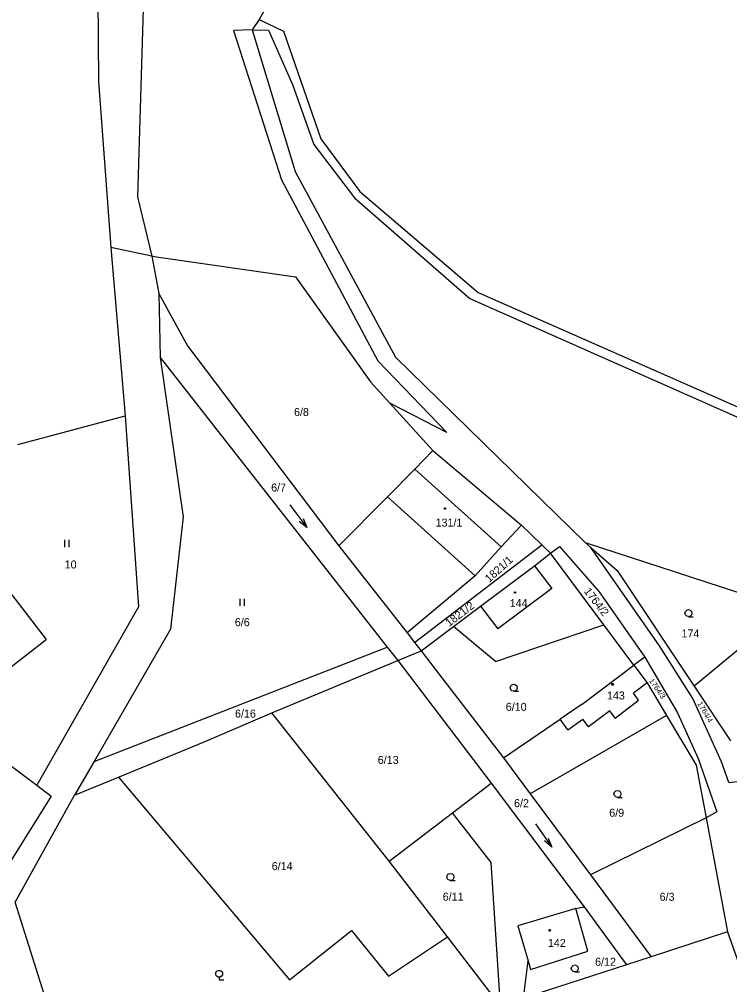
# Model space of a CAD drawing. Extents: x -799786 to -795190, y -1021716 to -1017834.
# Drawn here: x -797930.9 to -797780.2, y -1018913.6 to -1018708.6 of the extents above; entities that cross this region are included whole.
import ezdxf

# ---------------------------------------------------------------- set-up
doc = ezdxf.new("R2010")
doc.units = 0
for name, color, linetype in [('Default', 7, 'Continuous'), ('KN_HRANICE', 7, 'Continuous'), ('KN_KULTURY', 7, 'Continuous'), ('KN_PARCELY', 7, 'Continuous'), ('KN_SLUCKY', 7, 'Continuous')]:
    doc.layers.add(name, color=color, linetype=linetype)

# ---------------------------------------------------------------- blocks, each defined once
blk = doc.blocks.new('304')
at = {"layer": 'Default'}
blk.add_lwpolyline([(0, 0), (-0.38, 0.1), (-0.65, 0.37), (-0.75, 0.74), (-0.65, 1.11), (-0.38, 1.38), (-0.01, 1.48), (0.36, 1.38), (0.63, 1.11), (0.73, 0.73), (0.63, 0.35), (0.36, 0.08), (-0.02, -0.02), (0.98, -0.02)], dxfattribs=at)
blk = doc.blocks.new('305')
at = {"layer": 'Default'}
blk.add_lwpolyline([(0, 0.53), (-0.19, 0.53), (-0.53, 0.72), (-0.72, 1.06), (-0.72, 1.45), (-0.53, 1.79), (-0.19, 1.98), (0.2, 1.98), (0.54, 1.79), (0.73, 1.45), (0.73, 1.06), (0.54, 0.72), (0.2, 0.53), (0.01, 0.53), (0.01, 0), (1.01, 0)], dxfattribs=at)
blk = doc.blocks.new('306')
at = {"layer": 'Default'}
for p, q in [((-0.5, 1.5), (-0.5, 0)), ((0.5, 0), (0.5, 1.5))]:
    blk.add_line(p, q, dxfattribs=at)
blk = doc.blocks.new('802')
at = {"layer": 'Default'}
blk.add_line((-3, 0), (3, 0), dxfattribs=at)
blk.add_lwpolyline([(1, 0.5), (3, 0), (1, -0.5)], dxfattribs=at)
blk = doc.blocks.new('402')
at = {"layer": 'Default'}
blk.add_lwpolyline([(0.09, 0.15), (0.18, 0), (0.09, -0.15), (-0.09, -0.15), (-0.18, 0), (-0.09, 0.15), (0.09, 0.15)], dxfattribs=at)

msp = doc.modelspace()

# ---------------------------------------------------------------- linework, layer by layer
at = {"layer": 'KN_HRANICE'}
for p, q in [((-797902.79, -1018644.81), (-797905.77, -1018746.29)), ((-797914.78, -1018646.59), (-797914.05, -1018721.83)), ((-797878.74, -1018706.41), (-797879.96, -1018708.66)), ((-797879.96, -1018708.66), (-797881.5, -1018710.9)), ((-797879.96, -1018708.66), (-797874.8, -1018711.12)), ((-797881.5, -1018710.9), (-797885.45, -1018710.98)), ((-797885.45, -1018710.98), (-797875.25, -1018742.68)), ((-797881.5, -1018710.9), (-797878.03, -1018710.96)), ((-797881.5, -1018710.9), (-797872.36, -1018740.96)), ((-797878.03, -1018710.96), (-797872.93, -1018722.5)), ((-797874.8, -1018711.12), (-797866.9, -1018733.99)), ((-797914.05, -1018721.83), (-797911.48, -1018757.08)), ((-797872.93, -1018722.5), (-797868.41, -1018735.2)), ((-797868.41, -1018735.2), (-797859.73, -1018746.53)), ((-797866.9, -1018733.99), (-797858.62, -1018745.17)), ((-797872.36, -1018740.96), (-797851.04, -1018780.39)), ((-797875.25, -1018742.68), (-797854.8, -1018781.15)), ((-797858.62, -1018745.17), (-797833.49, -1018766.66)), ((-797905.77, -1018746.29), (-797902.78, -1018758.93)), ((-797859.73, -1018746.53), (-797835.29, -1018767.9)), ((-797911.48, -1018757.08), (-797908.42, -1018792.81)), ((-797902.78, -1018758.93), (-797901.25, -1018766.87)), ((-797902.78, -1018758.93), (-797872.27, -1018763.32)), ((-797872.27, -1018763.32), (-797856.35, -1018785.57)), ((-797901.25, -1018766.87), (-797901.03, -1018780.44)), ((-797901.25, -1018766.87), (-797895.18, -1018777.94)), ((-797835.29, -1018767.9), (-797771.75, -1018796.11)), ((-797833.49, -1018766.66), (-797771.73, -1018793.9)), ((-797895.18, -1018777.94), (-797863.08, -1018820.42)), ((-797901.03, -1018780.44), (-797896.14, -1018814.23)), ((-797901.03, -1018780.44), (-797852.81, -1018841.93)), ((-797851.04, -1018780.39), (-797810.84, -1018819.71)), ((-797854.8, -1018781.15), (-797840.2, -1018796.33)), ((-797856.35, -1018785.57), (-797852.27, -1018790.1)), ((-797852.27, -1018790.1), (-797843.13, -1018800.15)), ((-797840.2, -1018796.33), (-797852.27, -1018790.1)), ((-797931.22, -1018798.88), (-797908.42, -1018792.81)), ((-797908.42, -1018792.81), (-797905.56, -1018833.37)), ((-797843.13, -1018800.15), (-797846.98, -1018804.16)), ((-797843.13, -1018800.15), (-797824.36, -1018816.02)), ((-797846.98, -1018804.16), (-797852.79, -1018810.03)), ((-797947.79, -1018811.02), (-797925.16, -1018840.33)), ((-797852.79, -1018810.03), (-797863.08, -1018820.42)), ((-797896.14, -1018814.23), (-797898.83, -1018838.12)), ((-797828.64, -1018820.64), (-797824.36, -1018816.02)), ((-797824.36, -1018816.02), (-797820.02, -1018820.2)), ((-797810.84, -1018819.71), (-797771.98, -1018832.39)), ((-797810.84, -1018819.71), (-797809.64, -1018820.76)), ((-797863.08, -1018820.42), (-797848.62, -1018838.85)), ((-797847.01, -1018840.91), (-797820.02, -1018820.2)), ((-797828.64, -1018820.64), (-797834.15, -1018826.78)), ((-797820.02, -1018820.2), (-797818.19, -1018821.97)), ((-797809.64, -1018820.76), (-797804, -1018825.66)), ((-797795.03, -1018841.64), (-797809.64, -1018820.76)), ((-797821.59, -1018824.67), (-797818.19, -1018821.97)), ((-797806.87, -1018837.17), (-797818.19, -1018821.97)), ((-797833, -1018833.24), (-797821.59, -1018824.67)), ((-797804, -1018825.66), (-797787.67, -1018850.19)), ((-797834.15, -1018826.78), (-797848.62, -1018838.85)), ((-797905.56, -1018833.37), (-797927.17, -1018871.24)), ((-797838.74, -1018837.55), (-797833, -1018833.24)), ((-797898.83, -1018838.12), (-797915.03, -1018866.23)), ((-797845.6, -1018842.71), (-797838.74, -1018837.55)), ((-797829.85, -1018844.95), (-797838.74, -1018837.55)), ((-797829.85, -1018844.95), (-797806.87, -1018837.17)), ((-797800.5, -1018845.72), (-797806.87, -1018837.17)), ((-797933.51, -1018846.78), (-797925.16, -1018840.33)), ((-797848.62, -1018838.85), (-797847.01, -1018840.91)), ((-797774.28, -1018839.06), (-797787.67, -1018850.19)), ((-797915.03, -1018866.23), (-797852.81, -1018841.93)), ((-797852.81, -1018841.93), (-797850.58, -1018844.77)), ((-797847.01, -1018840.91), (-797845.6, -1018842.71)), ((-797787.96, -1018852.82), (-797795.03, -1018841.64)), ((-797850.58, -1018844.77), (-797845.6, -1018842.71)), ((-797845.6, -1018842.71), (-797841.91, -1018847.5)), ((-797798.16, -1018844.08), (-797800.5, -1018845.72)), ((-797877.33, -1018855.84), (-797850.58, -1018844.77)), ((-797850.58, -1018844.77), (-797830.78, -1018870.8)), ((-797811.46, -1018854.01), (-797800.5, -1018845.72)), ((-797800.5, -1018845.72), (-797797.7, -1018849.5)), ((-797841.91, -1018847.5), (-797828.13, -1018865.39)), ((-797797.7, -1018849.5), (-797793.56, -1018856.45)), ((-797787.67, -1018850.19), (-797779.96, -1018861.78)), ((-797811.46, -1018854.01), (-797816.16, -1018857.22)), ((-797781.88, -1018866.24), (-797787.96, -1018852.82)), ((-797888.8, -1018860.85), (-797877.33, -1018855.84)), ((-797852.4, -1018887.34), (-797877.33, -1018855.84)), ((-797793.56, -1018856.45), (-797822.46, -1018873.06)), ((-797793.56, -1018856.45), (-797787.29, -1018866.96)), ((-797828.13, -1018865.39), (-797816.16, -1018857.22)), ((-797909.84, -1018869.53), (-797891.81, -1018862.08)), ((-797891.81, -1018862.08), (-797888.8, -1018860.85)), ((-797934.53, -1018865.68), (-797927.17, -1018871.24)), ((-797915.03, -1018866.23), (-797919.15, -1018873.38)), ((-797828.13, -1018865.39), (-797822.46, -1018873.06)), ((-797787.29, -1018866.96), (-797785.17, -1018878.15)), ((-797780.36, -1018870.66), (-797781.88, -1018866.24)), ((-797919.15, -1018873.38), (-797909.84, -1018869.53)), ((-797909.84, -1018869.53), (-797873.59, -1018912.55)), ((-797839, -1018877.09), (-797830.78, -1018870.8)), ((-797830.78, -1018870.8), (-797811.04, -1018897.02)), ((-797780.36, -1018870.66), (-797776.1, -1018870.15)), ((-797927.17, -1018871.24), (-797924.14, -1018873.53)), ((-797822.46, -1018873.06), (-797809.72, -1018890.27)), ((-797924.14, -1018873.53), (-797947.51, -1018911.01)), ((-797931.74, -1018896.06), (-797919.15, -1018873.38)), ((-797852.4, -1018887.34), (-797839, -1018877.09)), ((-797830.76, -1018887.66), (-797839, -1018877.09)), ((-797785.17, -1018878.15), (-797809.72, -1018890.27)), ((-797785.17, -1018878.15), (-797780.6, -1018902.35)), ((-797840.06, -1018903.4), (-797852.4, -1018887.34)), ((-797828.8, -1018918.06), (-797830.76, -1018887.66)), ((-797809.72, -1018890.27), (-797796.84, -1018907.67)), ((-797921.5, -1018928.71), (-797931.74, -1018896.06)), ((-797812.83, -1018897.4), (-797811.04, -1018897.02)), ((-797810.28, -1018906.45), (-797812.83, -1018897.4)), ((-797811.04, -1018897.02), (-797802.04, -1018909.37)), ((-797873.59, -1018912.55), (-797860.43, -1018902.08)), ((-797860.43, -1018902.08), (-797852.53, -1018911.79)), ((-797852.53, -1018911.79), (-797840.06, -1018903.4)), ((-797828.8, -1018918.06), (-797840.06, -1018903.4)), ((-797780.6, -1018902.35), (-797796.84, -1018907.67)), ((-797780.6, -1018902.35), (-797774.45, -1018919.96)), ((-797822.39, -1018910.39), (-797810.28, -1018906.45)), ((-797796.84, -1018907.67), (-797802.04, -1018909.37)), ((-797823.92, -1018916.47), (-797822.94, -1018908.49)), ((-797802.04, -1018909.37), (-797823.92, -1018916.47)), ((-797822.94, -1018908.49), (-797822.39, -1018910.39))]:
    msp.add_line(p, q, dxfattribs=at)
for points in [[(-797818.19, -1018821.97), (-797816.27, -1018820.56), (-797807.83, -1018830.19), (-797798.16, -1018844.08)], [(-797798.16, -1018844.08), (-797791.21, -1018855.9), (-797786.82, -1018865.59), (-797782.9, -1018876.91), (-797785.17, -1018878.15)]]:
    msp.add_lwpolyline(points, dxfattribs=at)
at = {"layer": 'KN_SLUCKY'}
for p, q in [((-797902.78, -1018758.93), (-797911.48, -1018757.08)), ((-797846.98, -1018804.16), (-797828.64, -1018820.64)), ((-797852.79, -1018810.03), (-797834.15, -1018826.78)), ((-797821.59, -1018824.67), (-797817.91, -1018829.47)), ((-797817.91, -1018829.47), (-797829.33, -1018838.02)), ((-797833, -1018833.24), (-797829.33, -1018838.02)), ((-797797.7, -1018849.5), (-797800.6, -1018851.69)), ((-797799.49, -1018853.19), (-797800.6, -1018851.69)), ((-797804.49, -1018856.97), (-797799.49, -1018853.19)), ((-797805.6, -1018855.46), (-797808.67, -1018857.78)), ((-797804.49, -1018856.97), (-797805.6, -1018855.46)), ((-797814.47, -1018859.51), (-797816.16, -1018857.22)), ((-797814.47, -1018859.51), (-797811.34, -1018857.18)), ((-797810.1, -1018858.86), (-797811.34, -1018857.18)), ((-797808.67, -1018857.78), (-797810.1, -1018858.86)), ((-797812.83, -1018897.4), (-797825.09, -1018901.07)), ((-797825.09, -1018901.07), (-797822.94, -1018908.49))]:
    msp.add_line(p, q, dxfattribs=at)

# ---------------------------------------------------------------- block references
at = {"layer": 'KN_KULTURY'}
for p, rotation in [((-797871.68, -1018814.14), -53.23839600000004), ((-797819.63, -1018881.92), -55.301045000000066)]:
    msp.add_blockref('802', p, dxfattribs=dict(at, rotation=rotation))
for name, p in [('402', (-797840.57, -1018812.47)), ('306', (-797920.8, -1018820.67)), ('306', (-797883.58, -1018833.17)), ('402', (-797825.7, -1018830.3)), ('304', (-797788.9, -1018835.44)), ('304', (-797825.97, -1018851.27)), ('402', (-797805.02, -1018849.81)), ('304', (-797803.96, -1018873.82)), ('304', (-797839.41, -1018891.45)), ('402', (-797818.37, -1018902.05)), ('304', (-797813.01, -1018910.87)), ('305', (-797888.5, -1018912.53))]:
    msp.add_blockref(name, p, dxfattribs=at)

# ---------------------------------------------------------------- texts
at = {"layer": 'KN_PARCELY'}
for s, p in [('6/8', (-797872.6, -1018792.86)), ('6/7', (-797877.45, -1018808.89)), ('131/1', (-797842.56, -1018816.34)), ('10', (-797921.26, -1018825.22)), ('144', (-797826.84, -1018833.43)), ('6/6', (-797885.15, -1018837.47)), ('174', (-797790.38, -1018839.87)), ('143', (-797806.2, -1018853.03)), ('6/10', (-797827.67, -1018855.44)), ('6/16', (-797885.12, -1018856.88)), ('6/13', (-797854.83, -1018866.72)), ('6/2', (-797825.91, -1018875.9)), ('6/9', (-797805.72, -1018877.93)), ('6/14', (-797877.32, -1018889.25)), ('6/11', (-797841.04, -1018895.75)), ('6/3', (-797795.02, -1018895.77)), ('142', (-797818.73, -1018905.57)), ('6/12', (-797808.72, -1018909.56))]:
    msp.add_text(s, height=1.7, dxfattribs=at).set_placement(p)
for s, height, rotation, p in [('1821/1', 1.7, 42.284, (-797831.15, -1018828.29)), ('1764/2', 1.68, 307.85, (-797811.18, -1018830.1)), ('1821/2', 1.7, 37.471, (-797839.68, -1018837.67)), ('1764/3', 1.14, 304.814, (-797797.33, -1018849.07)), ('1764/4', 1.14, 300.631, (-797787.07, -1018853.91))]:
    msp.add_text(s, height=height, rotation=rotation, dxfattribs=at).set_placement(p)

doc.saveas('drawing.dxf')
